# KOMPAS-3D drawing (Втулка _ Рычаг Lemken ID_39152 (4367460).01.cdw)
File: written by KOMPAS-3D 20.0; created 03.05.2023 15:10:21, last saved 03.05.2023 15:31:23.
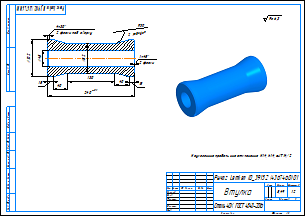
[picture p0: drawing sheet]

Sheet 1: A3, landscape

Document properties: Автор: factory; Масса: 8.491

Title block, sheet 1: Наименование: Втулка; designation: Рычаг Lemken ID_39152 (4367460).01; Материал: Сталь 40Х  ГОСТ 4543-2016; Масса: 8,49; Количество листов документа: 1; Форматы листов документа: A3; stored path: C:\Users\factory\Desktop\Чертежи\Рычаг Lemken ID_39152 (4367460)\Втулка _ Рычаг Lemken ID_39152 (4367460).01.cdw

Views: Вид 1
Referenced files in C:\Users\factory\Desktop\Чертежи\Рычаг Lemken ID_39152 (4367460)\: Втулка _ Рычаг Lemken ID_39152 (4367460).01_Рис.jpg
Referenced files in C:\Users\factory\AppData\Roaming\Ascon\KOMPAS-3D\20\SHAFT\: Деталь (типа вал-шестерня).m3d
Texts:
  Неуказанные предельные отклонения H14, h14, ±JT14/2.
  Втулка _ Рычаг Lemken ID_39152 (4367460).01_Рис.jpg
  Ra 6,3
  Точечный пунктир
  gliv
Dimensions and other numbers on the sheet: 240; 15; 40; 130; 102; 82; 45; 4; 2 фаски под сварку; 1; 2 фаски; 30; 2 радиуса; 1:2; 8,49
